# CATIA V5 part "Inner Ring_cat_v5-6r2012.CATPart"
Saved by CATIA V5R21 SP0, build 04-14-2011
Part number: Inner Ring
Bounding box of the stored display mesh (mm): x -69.981 to 69.981, y 0 to 50, z -69.908 to 69.908
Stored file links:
  D:\CATIA V5R21 E-RESOURCES\CATIA-V5R21\catia-v5r21-Tut\c16-catia-v5r21-tut\c16-catia-v5r21-tut04\Inner Ring_cat_v5r21.CATPart
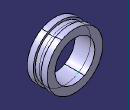
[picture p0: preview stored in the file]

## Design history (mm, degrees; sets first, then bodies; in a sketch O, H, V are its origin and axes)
Body1 (main body)
  Sketch1 on yz-plane, origin (0, 0, 0), H (0, 1, 0), V (0, 0, 1)
    point P1 (0, 50)
    line L1 (0, 50) -> (0, 70)
    line L2 (0, 70) -> (15, 70)
    line L3 (15, 70) -> (15, 65)
    line L4 (15, 65) -> (35, 65)
    line L5 (35, 65) -> (35, 70)
    point P6 (35, 70)
    line L6 (35, 70) -> (50, 70)
    line L7 (50, 70) -> (50, 50)
    line L8 (50, 50) -> (0, 50)
    distance L8 H = 50
    length L8 = 50
    length L6 = 15
    length L2 = 15
    length L7 = 20
    distance L8 L4 = 15
    coincidence: P1 V, P6 L2
    vertical: L1 V, L3 V, L5 V, L7 V
    horizontal: L2 H, L4 H, L6 H, L8 H
  Shaft1: profile Sketch1, axis Sketch1.H, angle 360
  Plane1: type Offset, RefPlane face of Shaft1 from Sketch1.L3, Offset 10, reversed
  Sketch2 on Plane1, origin (0, 25, 0), H (1, 0, 0), V (0, 0, 1)
    projected circle E1 centre (0, 0) radius 65 from edge [face of Shaft1 from Sketch1.L4 | face of Shaft1 from Sketch1.L5]
  Point1: type OnCurve, Support Sketch2, RefPoint {extremum Reference Sketch2, Direction (1, 2, 3)}, Length 192.617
